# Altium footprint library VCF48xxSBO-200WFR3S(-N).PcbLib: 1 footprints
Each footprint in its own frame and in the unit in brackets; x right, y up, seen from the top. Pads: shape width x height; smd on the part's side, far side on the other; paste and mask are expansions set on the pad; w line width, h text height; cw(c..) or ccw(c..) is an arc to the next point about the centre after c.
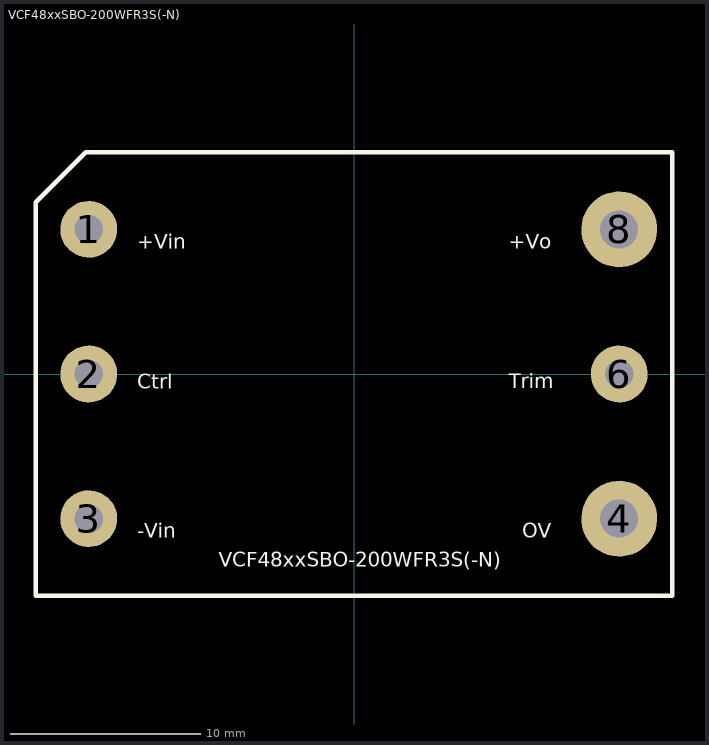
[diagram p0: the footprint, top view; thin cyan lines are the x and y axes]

## VCF48xxSBO-200WFR3S(-N) [mm]
pads (6):
  round 3 hole 1.5: 1(-13.97,7.62) 2(-13.97,0) 3(-13.97,-7.62) 6(13.97,0)
  round 4 hole 2: 4(13.97,-7.62) 8(13.97,7.62)
Top Overlay:
  lines w0.254: -16.76,-11.68 16.76,-11.68 16.76,11.68 -14.13,11.68 -16.76,9.05 -16.76,-11.68
  text "+Vo" at 8.161,6.604 h0.76
  text "Trim" at 8.153,-0.762 h0.76
  text "OV" at 8.85,-8.636 h0.76
  text "-Vin" at -11.43,-8.636 h0.76
  text "Ctrl" at -11.428,-0.781 h0.76
  text "+Vin" at -11.43,6.604 h0.76
  text "VCF48xxSBO-200WFR3S(-N)" at -7.112,-10.16 h0.76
